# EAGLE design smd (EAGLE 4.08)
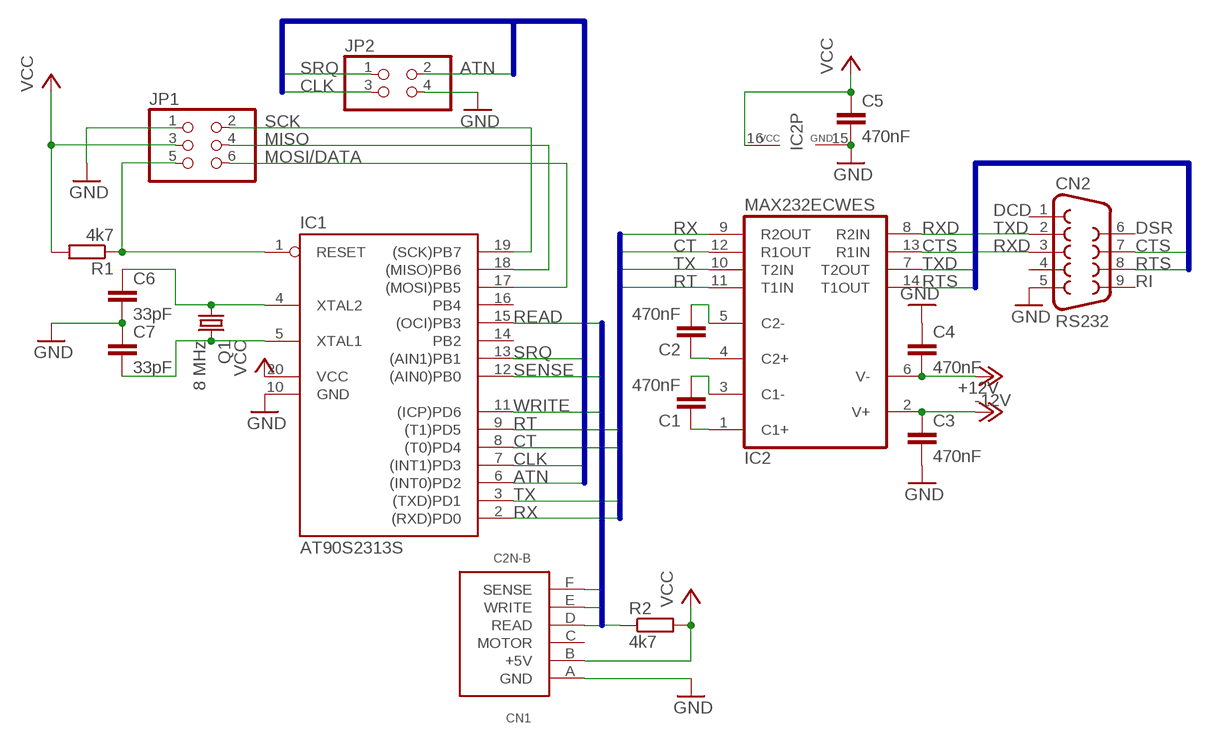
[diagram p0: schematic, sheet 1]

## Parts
C1  470nF  C-EUC0805  [C0805]
C2  470nF  C-EUC0805  [C0805]
C3  470nF  C-EUC0805  [C0805]
C4  470nF  C-EUC0805  [C0805]
C5  470nF  C-EUC0805  [C0805]
C6  33pF  C-EUC0805  [C0805]
C7  33pF  C-EUC0805  [C0805]
CN1  C2N-B  [C2N-B]
CN2  RS232  F09D  [F09D]
IC1  AT90S2313S  [SO-20L]
IC2  MAX232ECWES  [SO16]
JP1  PINHD-2X3  [2X03]
JP2  PINHD-2X2  [2X02]
Q1  8 MHz  SM49  [SM49]
R1  4k7  R-EU_R0805  [R0805]
R2  4k7  R-EU_R0805  [R0805]

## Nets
+12V: C3.2 IC2.2(V+)
-12V: C4.1 IC2.6(V-)
ATN: IC1.6((INT0)PD2) JP2.2
C1+: C1.2 IC2.1(C1+)
C1-: C1.1 IC2.3(C1-)
C2+: C2.2 IC2.4(C2+)
C2-: C2.1 IC2.5(C2-)
CLK: IC1.7((INT1)PD3) JP2.3
CT: IC1.8((T0)PD4) IC2.12(R1OUT)
CTS: CN2.7 IC2.13(R1IN)
GND: C3.1 C4.2 C5.1 C6.1 C7.2 CN1.A(GND) CN2.5 IC1.10(GND) IC2.15(GND) JP1.1 JP2.4
MISO: IC1.18((MISO)PB6) JP1.4
MOSI/DATA: IC1.17((MOSI)PB5) JP1.6
READ: CN1.D(READ) IC1.15((OCI)PB3) R2.1
RESET: IC1.1(RESET) JP1.5 R1.1
RT: IC1.9((T1)PD5) IC2.11(T1IN)
RTS: CN2.8 IC2.14(T1OUT)
RX: IC1.2((RXD)PD0) IC2.9(R2OUT)
RXD: CN2.3 IC2.8(R2IN)
SCK: IC1.19((SCK)PB7) JP1.2
SENSE: CN1.F(SENSE) IC1.12((AIN0)PB0)
SRQ: IC1.13((AIN1)PB1) JP2.1
TX: IC1.3((TXD)PD1) IC2.10(T2IN)
TXD: CN2.2 IC2.7(T2OUT)
VCC: C5.2 CN1.B(+5V) IC1.20(VCC) IC2.16(VCC) JP1.3 R1.2 R2.2
WRITE: CN1.E(WRITE) IC1.11((ICP)PD6)
XTAL1: C7.1 IC1.5(XTAL1) Q1.2
XTAL2: C6.2 IC1.4(XTAL2) Q1.1
Unconnected: CN1.C(MOTOR) CN2.1 CN2.4 CN2.6 CN2.9 IC1.14(PB2) IC1.16(PB4)

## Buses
WRITE,READ,SENSE,MOTOR
DTR,CTS,RTS,RXD,TXD,DSR,RI,DCD
RX,TX,CT,RT
ATN,CLK,DATA,SRQ

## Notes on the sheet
- DCD
- DSR
- RI

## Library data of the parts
C1-C7 = rcl:C-EU: CAPACITOR, European symbol
CN1 = vic-20:C2N: Datassette connector
CN2 = con-subd:F09D: HARTING SUB-D
IC1 = atmel:AT90S2313: MICROCONTROLLER 2 Kbytes FLASH 128 bytes SRAM 128 bytes EEPROM UART
IC2 = maxim:MAX232ECWE: RS232 TRANSCEIVER
JP1 = pinhead:PINHD-2X3: PIN HEADER
JP2 = pinhead:PINHD-2X2: PIN HEADER
Q1 = crystal:SM49: CRYSTAL
R1 R2 = rcl:R-EU_: RESISTOR, European symbol

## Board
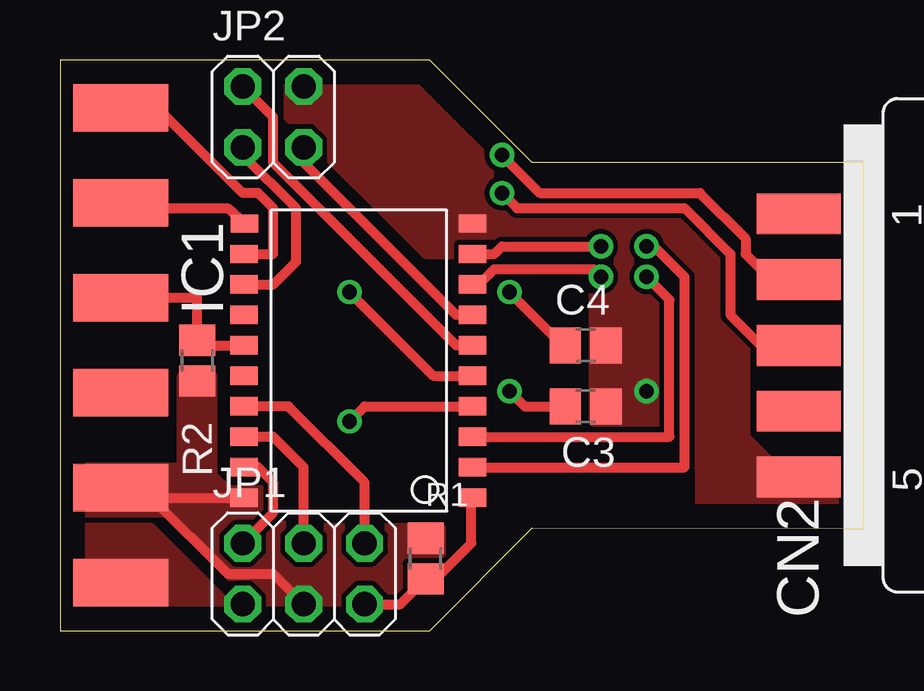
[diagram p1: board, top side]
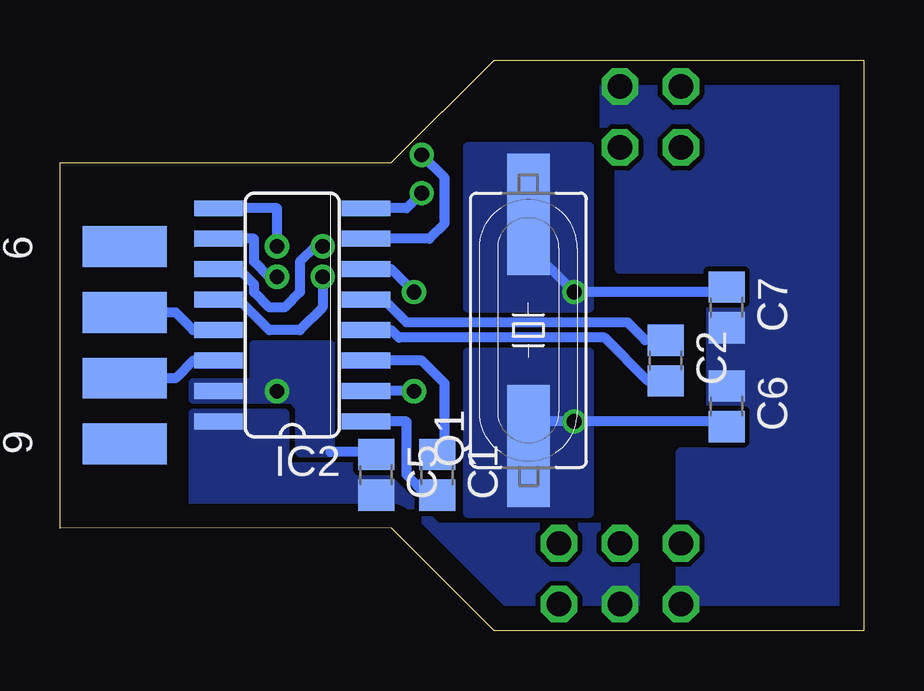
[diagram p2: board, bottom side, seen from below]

Size 33.48 x 23.8 mm. Coordinates in mm from the lower left corner, seen from the top.
Outline: 0,23.8 0,0 15.4,0 19.68,4.28 33.48,4.28 33.48,19.53 33.02,19.53 33.02,19.52 19.68,19.52 15.4,23.8 0,23.8
Copper layers used: Top, Bottom

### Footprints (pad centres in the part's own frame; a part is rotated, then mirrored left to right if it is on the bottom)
C0805 = smd 1.3 x 1.5: 1 -0.85,0; 2 0.85,0
C2N-B = smd 1.98 x 3.96 bottom: A -9.9,0; B -5.94,0; C -1.98,0; D 1.98,0; E 5.94,0; F 9.9,0
F09D = smd 1.7 x 3.5: 1 -5.486,-6.045; 2 -2.743,-6.045; 3 0,-6.045; 4 2.743,-6.045; 5 5.486,-6.045 | smd 1.7 x 3.5 bottom: 6 -4.115,-6.045; 7 -1.372,-6.045; 8 1.372,-6.045; 9 4.115,-6.045
SO-20L = smd 0.762 x 1.143: 1 -5.08,-5.131; 2 -3.81,-5.131; 3 -2.54,-5.131; 4 -1.27,-5.131; 5 0,-5.131; 6 1.27,-5.131; 7 2.54,-5.131; 8 3.81,-5.131; 9 5.08,-5.131; 10 6.35,-5.131; 11 6.35,4.369; 12 5.08,4.394; 13 3.81,4.394; 14 2.54,4.394; 15 1.27,4.394; 16 0,4.394; 17 -1.27,4.394; 18 -2.54,4.394; 19 -3.81,4.394; 20 -5.08,4.394
SO16 = smd 0.66 x 2.032: 1 -4.445,-3.073; 2 -3.175,-3.073; 3 -1.905,-3.073; 4 -0.635,-3.073; 5 0.635,-3.073; 6 1.905,-3.073; 7 3.175,-3.073; 8 4.445,-3.073; 9 4.445,3.073; 10 3.175,3.073; 11 1.905,3.073; 12 0.635,3.073; 13 -0.635,3.073; 14 -1.905,3.073; 15 -3.175,3.073; 16 -4.445,3.073
2X03 = drill 1.016 octagon: 1 -2.54,-1.27; 2 -2.54,1.27; 3 0,-1.27; 4 0,1.27; 5 2.54,-1.27; 6 2.54,1.27
2X02 = drill 1.016 octagon: 1 -1.27,-1.27; 2 -1.27,1.27; 3 1.27,-1.27; 4 1.27,1.27
SM49 = smd 5.08 x 1.778: 1 -4.826,0; 2 4.826,0
R0805 = smd 1.3 x 1.5: 1 -0.85,0; 2 0.85,0

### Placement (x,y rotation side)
C1  17.78,6.5 270 bottom
C2  8.25,11.27 270 bottom
C3  21.9,9.36 180 top
C4  21.9,11.9 0 top
C5  20.32,6.5 270 bottom
C6  5.71,9.36 270 bottom
C7  5.71,13.49 270 bottom
CN1  2.54,11.9 90 bottom
CN2  36.82,11.9 270 top
IC1  12.06,10.63 90 top
IC2  23.81,13.17 90 bottom
JP1  10.15,2.38 0 top
JP2  8.88,21.43 0 top
Q1  13.96,12.54 90 bottom
R1  15.23,3.01 90 top
R2  5.71,11.27 270 top

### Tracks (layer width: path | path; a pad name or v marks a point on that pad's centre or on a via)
+12V  (via drill 0.61 pad 0.61)
  Top 0.406: v18.73,10 19.36,9.36 C3.2
  Bottom 0.406: v18.73,10 IC2.2
-12V  (via drill 0.61 pad 0.61)
  Top 0.406: C4.1 20.95,11.9 v18.73,14.12
  Bottom 0.406: v18.73,14.12 19.68,15.08 IC2.6
ATN
  Top 0.406: IC1.6 16.51,11.9 8.88,19.52 8.88,21.43 JP2.2
C1+
  Bottom 0.406: C1.2 18.2,5.65 19.05,6.5 19.05,8.73 IC2.1
C1-
  Bottom 0.406: IC2.3 18.41,11.27 17.46,10.31 17.46,7.35 C1.1
C2+
  Bottom 0.406: C2.2 8.99,10.42 10.79,12.22 19.36,12.22 19.68,12.54 IC2.4
C2-
  Bottom 0.406: C2.1 9.1,12.12 9.84,12.85 19.05,12.85 20,13.81 IC2.5
CLK
  Top 0.406: IC1.7 16.51,13.17 10.15,19.52 JP2.3
CT  (via drill 0.61 pad 0.61)
  Top 0.406: IC1.8 17.46,14.44 18.09,15.08 22.22,15.08 v22.54,14.76
  Bottom 0.406: v22.54,14.76 22.54,13.49 23.49,12.54 24.76,12.54 26.03,13.81 IC2.12
CTS
  Bottom 0.406: IC2.13 27.94,12.54 28.67,13.27 CN2.7
GND  (via drill 0.61)
  Bottom 0.406: C5.1 20.42,7.46 22.22,7.46
  other vias: 24.44,10
  pour Bottom (no thermals): -0.01,-0.17 7.62,-0.17 7.62,7.46 6.34,7.46 6.34,13.49 4.76,13.49 4.76,15.08 10.15,15.08 10.15,20.16 10.79,20.16 10.79,23.96 -0.01,23.96
  pour Top (no thermals): 22.22,8.73 24.76,8.73 26.67,6.82 26.67,4.28 32.38,4.28 32.38,6.82 29.84,6.82 28.57,8.09 28.57,11.9 27.94,12.54 27.94,15.08 25.39,17.62 22.22,17.62
  pour Top (no thermals): 22.22,17.62 20.95,17.62 15.23,23.33 9.52,23.33 9.52,21.43 15.23,15.71 20.32,15.71 22.22,13.81
  pour Top (no thermals): 8.25,-0.17 3.81,4.28 -0.01,4.28 -0.01,-0.17
  pour Bottom (no thermals): 25.39,10.31 27.94,10.31 27.94,9.68 23.81,9.68 23.49,9.36 23.49,7.46 22.22,7.46 22.22,11.9 25.39,11.9
MISO
  Top 0.406: IC1.18 8.88,8.09 10.15,6.82 JP1.4
MOSI/DATA
  Top 0.406: IC1.17 9.52,9.36 12.69,6.18 JP1.6
READ
  Top 0.406: 5.71,11.9 IC1.15 | R2.1 5.71,11.9 | CN1.D 5.71,13.88 5.71,11.9
RESET
  Top 0.406: IC1.1 17.14,5.55 17.14,3.65 15.65,2.16 R1.1 14.18,1.1 JP1.5
RT  (via drill 0.61 pad 0.61)
  Top 0.406: IC1.9 18.09,15.71 18.41,16.03 v22.54,16.03
  Bottom 0.406: v22.54,16.03 22.86,16.03 23.49,15.39 23.49,14.12 24.12,13.49 24.76,13.49 25.39,14.12 25.39,14.44 26.03,15.08 IC2.11
RTS
  Bottom 0.406: CN2.8 28.67,10.53 27.94,11.27 IC2.14
RX  (via drill 0.61 pad 0.61)
  Top 0.406: IC1.2 26.03,6.82 26.03,14.76 24.76,16.03 v24.44,16.03
  Bottom 0.406: v24.44,16.03 24.44,17.62 IC2.9 27.3,17.62
RXD  (via drill 0.61 pad 0.61)
  Top 0.406: v18.41,18.25 19.05,17.62 26.03,17.62 27.94,15.71 27.94,13.17 29.21,11.9 CN2.3
  Bottom 0.406: v18.41,18.25 19.05,17.62 IC2.8
SCK
  Top 0.406: IC1.19 8.25,6.82 8.88,6.18 8.88,4.92 JP1.2
SENSE
  Top 0.406: CN1.F 2.54,22.06 3.81,22.06 7.62,18.25 8.25,18.25 8.88,17.62 8.88,15.71 IC1.12
SRQ
  Top 0.406: IC1.13 8.88,14.44 9.84,15.39 9.84,17.62 7.62,19.84 JP2.1
TX  (via drill 0.61 pad 0.61)
  Top 0.406: IC1.3 25.39,8.09 25.39,13.81 v24.44,14.76
  Bottom 0.406: v24.44,14.76 24.76,14.76 25.39,15.39 25.39,16.35 IC2.10
TXD  (via drill 0.61 pad 0.61)
  Top 0.406: v18.41,19.84 20,18.25 26.67,18.25 28.57,16.35 28.57,15.71 29.64,14.64 CN2.2
  Bottom 0.406: v18.41,19.84 17.46,18.89 17.46,16.98 18.09,16.35 IC2.7
VCC
  Top 0.406: JP1.3 8.88,2.38 6.98,2.38 3.81,5.55 IC1.20
  Bottom 0.406: IC2.16 27.3,8.73
  pour Top (no thermals): 8.25,4.92 0.63,4.92 0.63,6.82 5.08,6.82 5.08,10.63 6.34,10.63 6.34,6.5 6.98,5.87 8.25,5.87
  pour Bottom (no thermals): 24.12,9.04 27.94,9.04 27.94,4.28 19.68,4.28 15.23,-0.17 9.52,-0.17 9.52,4.28 17.78,4.28 20.32,6.82 24.12,6.82
  pour Top (no thermals): 9.52,-0.17 4.76,4.6 4.76,5.87 9.2,5.87 9.2,4.28 15.87,4.28 15.87,-0.17
WRITE
  Top 0.406: CN1.E 2.54,17.62 6.98,17.62 IC1.11
XTAL1  (via drill 0.61)
  Top 0.406: IC1.5 15.55,10.63 v12.06,14.12
  Bottom 0.406: Q1.2 13.96,16.03 v12.06,14.12 5.71,14.12 C7.1
  pour Bottom (no thermals): 11.42,20.16 16.51,20.16 16.51,13.49 11.42,13.49
XTAL2  (via drill 0.61)
  Top 0.406: IC1.4 12.69,9.36 v12.06,8.73
  Bottom 0.406: C6.2 5.71,8.73 v12.06,8.73 13.96,8.73 Q1.1
  pour Bottom (no thermals): 11.42,11.58 16.51,11.58 16.51,4.92 11.42,4.92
